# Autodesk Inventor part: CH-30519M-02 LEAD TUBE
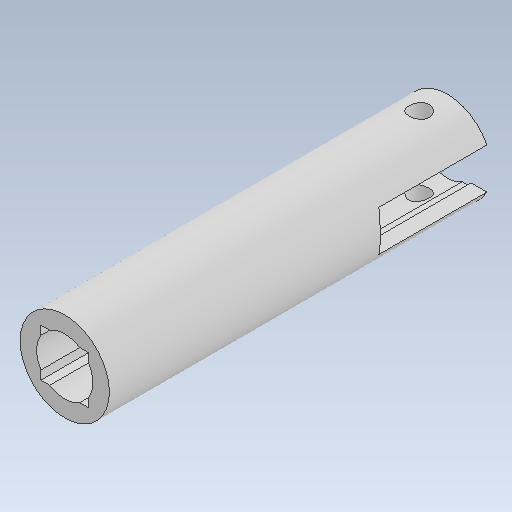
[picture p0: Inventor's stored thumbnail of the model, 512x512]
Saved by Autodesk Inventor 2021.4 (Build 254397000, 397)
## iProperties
Created: 2017-11
Part Number: CH-30519M-02 LEAD TUBE
Material: Ogólny
Document SubType Name: Modeling
Designer: user
Density: 1 g/cm^3
Appearance: Domyślna
Author: user
Revision Number: ÈÎºÎ
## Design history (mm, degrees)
feature "À­Éì4"
node "Bryła1"
